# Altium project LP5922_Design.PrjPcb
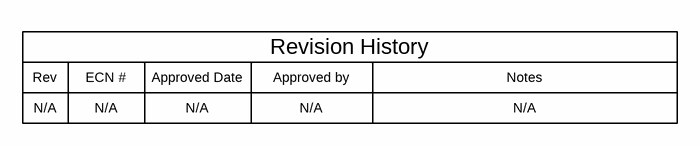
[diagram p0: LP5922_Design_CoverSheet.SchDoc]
CopyrightYear: 2016; PCB_Layout: Jari Niemelä; PCB_Rev: E1; PRJ_Customer: Public Release; PRJ_Engineer: Jari Niemelä; PRJ_Number: TIDA-01322; PRJ_Title: TIDA-01322; SCH_Rev: E1; TechSupport: http://www.ti.com/support; TID: N/A
3 sheets, 58 parts. Net scope: global (net labels, ports and power ports of the same name join across sheets).
Board file: LP5922_Design_PCB.PcbDoc
Sheets:
  LP5922_Design_CoverSheet.SchDoc
  LP5922_Design_BlankSheet.SchDoc
  LP5922_Design_EVM_Hardware.SchDoc

## Sheet LP5922_Design_CoverSheet.SchDoc
size 431 x 279 mm; Date: Not shown in title block; ApprovedBy: Not shown in title block; CheckedBy: Not shown in title block; Author: Not shown in title block; CompanyName: Not shown in title block; Engineer: Not shown in title block; Organization: Not shown in title block; Address1: Not shown in title block; Address2: Not shown in title block; Address3: Not shown in title block; Address4: Not shown in title block; DocumentNumber: 1; Revision: Use project parameter SCH_Rev; SheetNumber: 1; SheetTotal: 3; PageSetup: Record=PageOptions¦CenterHorizontal=True¦CenterVertical=True¦PrintScale=1.00¦XCorrection=1.00¦YCorrection=1.00¦PrintKind=0¦BorderSize=5000000¦LeftOffset=0¦BottomOffset=0¦Orientation=2¦PaperLength=1000¦PaperWidth=1000¦Scale=100¦PaperSource=15¦PrintQuality=600¦MediaType=1¦DitherType=10¦PaperKind=Letter¦PrintScaleMode=1

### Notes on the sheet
- Rev
- N/A
- ECN #
- Approved Date
- Approved by
- Revision History
- Notes

## Sheet LP5922_Design_BlankSheet.SchDoc
size 431 x 279 mm; Date: Not shown in title block; ApprovedBy: Not shown in title block; CheckedBy: Not shown in title block; Author: Not shown in title block; CompanyName: Not shown in title block; Engineer: Not shown in title block; Organization: Not shown in title block; Address1: Not shown in title block; Address2: Not shown in title block; Address3: Not shown in title block; Address4: Not shown in title block; DocumentNumber: 1; Revision: Use project parameter SCH_Rev; SheetNumber: 2; SheetTotal: 3; PageSetup: Record=PageOptions¦CenterHorizontal=True¦CenterVertical=True¦PrintScale=1.00¦XCorrection=1.00¦YCorrection=1.00¦PrintKind=0¦BorderSize=5000000¦LeftOffset=0¦BottomOffset=0¦Orientation=2¦PaperLength=1000¦PaperWidth=1000¦Scale=100¦PaperSource=15¦PrintQuality=600¦MediaType=1¦DitherType=10¦PrintScaleMode=1¦PaperKind=Letter
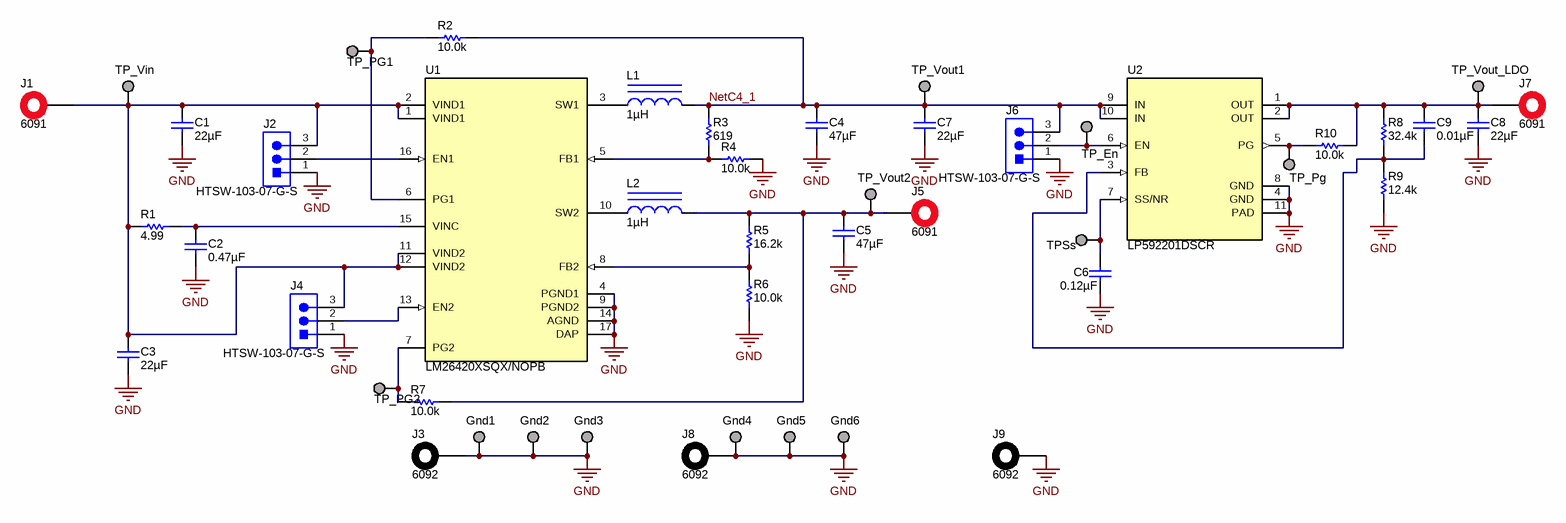
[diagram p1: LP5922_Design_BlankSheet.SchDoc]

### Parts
C1  ValueDisplayed: 22µF  [1206]  (hidden comment: C3216X5R0J226M)
C2  ValueDisplayed: 0.47µF  [0805_HV]  (hidden comment: 0805YC474JAT2A)
C3  ValueDisplayed: 22µF  [1206]  (hidden comment: C3216X5R0J226M)
C4  ValueDisplayed: 47µF  [1206]  (hidden comment: C3216X5R0J476M)
C5  ValueDisplayed: 47µF  [1206]  (hidden comment: C3216X5R0J476M)
C6  ValueDisplayed: 0.12µF  [0603]  (hidden comment: GRM188R71A124KA01D)
C7  ValueDisplayed: 22µF  [1210]  (hidden comment: C1210C226K9RACTU)
C8  ValueDisplayed: 22µF  [1210]  (hidden comment: C1210C226K9RACTU)
C9  ValueDisplayed: 0.01µF  [0603]  (hidden comment: GRM188R71H103KA01D)
Gnd1  Suggest using a net name here  [Keystone1502-2]  (value not drawn)
Gnd2  Suggest using a net name here  [Keystone1502-2]  (value not drawn)
Gnd3  Suggest using a net name here  [Keystone1502-2]  (value not drawn)
Gnd4  Suggest using a net name here  [Keystone1502-2]  (value not drawn)
Gnd5  Suggest using a net name here  [Keystone1502-2]  (value not drawn)
Gnd6  Suggest using a net name here  [Keystone1502-2]  (value not drawn)
J1  6091  [6091]
J2  HTSW-103-07-G-S  [Samtec_HTSW-103-07-G-S]
J3  6092  [6092]
J4  HTSW-103-07-G-S  [Samtec_HTSW-103-07-G-S]
J5  6091  [6091]
J6  HTSW-103-07-G-S  [Samtec_HTSW-103-07-G-S]
J7  6091  [6091]
J8  6092  [6092]
J9  6092  [6092]
L1  ValueDisplayed: 1µH  [DFE252012P]  (hidden comment: DFE252012PD-1R0M)
L2  ValueDisplayed: 1µH  [DFE252012P]  (hidden comment: DFE252012PD-1R0M)
R1  ValueDisplayed: 4.99  [0805_HV]  (hidden comment: CRCW08054R99FKEA)
R2  ValueDisplayed: 10.0k  [0402]  (hidden comment: CRCW040210K0DHEDP)
R3  ValueDisplayed: 619  [0402]  (hidden comment: CRCW0402619RFKED)
R4  ValueDisplayed: 10.0k  [0402]  (hidden comment: CRCW040210K0DHEDP)
R5  ValueDisplayed: 16.2k  [0402]  (hidden comment: CRCW040216K2FKED)
R6  ValueDisplayed: 10.0k  [0402]  (hidden comment: CRCW040210K0DHEDP)
R7  ValueDisplayed: 10.0k  [0402]  (hidden comment: CRCW040210K0DHEDP)
R8  ValueDisplayed: 32.4k  [0402]  (hidden comment: CRCW040232K4FKED)
R9  ValueDisplayed: 12.4k  [0402]  (hidden comment: CRCW040212K4FKED)
R10  ValueDisplayed: 10.0k  [0402]  (hidden comment: CRCW040210K0DHEDP)
TP_En  Suggest using a net name here  [Keystone1502-2]  (value not drawn)
TP_Pg  Suggest using a net name here  [Keystone1502-2]  (value not drawn)
TP_PG1  Suggest using a net name here  [Keystone1502-2]  (value not drawn)
TP_PG2  Suggest using a net name here  [Keystone1502-2]  (value not drawn)
TP_Vin  Suggest using a net name here  [Keystone1502-2]  (value not drawn)
TP_Vout1  Suggest using a net name here  [Keystone1502-2]  (value not drawn)
TP_Vout2  Suggest using a net name here  [Keystone1502-2]  (value not drawn)
TP_Vout_LDO  Suggest using a net name here  [Keystone1502-2]  (value not drawn)
TPSs  Suggest using a net name here  [Keystone1502-2]  (value not drawn)
U1  LM26420XSQX/NOPB  [RUM0016A]
U2  LP592201DSCR  [DSC0010J]

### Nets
GND: C1.2 C2.2 C3.2 C4.2 C5.2 C6.2 C7.2 C8.2 Gnd1.1 Gnd2.1 Gnd3.1 Gnd4.1 Gnd5.1 Gnd6.1 J2.1 J3.1 J4.1 J6.1 J8.1 J9.1 R4.1 R6.1 R9.1 U1.4(PGND1) U1.9(PGND2) U1.14(AGND) U1.17(DAP) U2.4(GND) U2.8(GND) U2.11(PAD)
NetC4_1: C4.1 C7.1 J6.3 L1.2 R2.2 R3.2 TP_Vout1.1 U2.9(IN) U2.10(IN)
NetC1_1: C1.1 C3.1 J1.1 J2.3 J4.3 R1.1 TP_Vin.1 U1.1(VIND1) U1.2(VIND1) U1.11(VIND2) U1.12(VIND2)
NetC2_1: C2.1 R1.2 U1.15(VINC)
NetC5_1: C5.1 J5.1 L2.2 R5.2 R7.2 TP_Vout2.1
NetC6_1: C6.1 TPSs.1 U2.7(SS/NR)
NetC8_1: C8.1 C9.1 J7.1 R8.2 R10.2 TP_Vout_LDO.1 U2.1(OUT) U2.2(OUT)
NetC9_2: C9.2 R8.1 R9.2 U2.3(FB)
NetJ2_2: J2.2 U1.16(EN1)
NetJ4_2: J4.2 U1.13(EN2)
NetJ6_2: J6.2 TP_En.1 U2.6(EN)
NetL1_1: L1.1 U1.3(SW1)
NetL2_1: L2.1 U1.10(SW2)
NetR2_1: R2.1 TP_PG1.1 U1.6(PG1)
NetR3_1: R3.1 R4.2 U1.5(FB1)
NetR5_1: R5.1 R6.2 U1.8(FB2)
NetR7_1: R7.1 TP_PG2.1 U1.7(PG2)
NetR10_1: R10.1 TP_Pg.1 U2.5(PG)

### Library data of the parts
C1 C3 = C3216X5R0J226M: CAP, CERM, 22 µF, 6.3 V, +/- 20%, X5R, 1206; Manufacturer: TDK; Polarized: N; CompType: Capacitor; Value: 22uF; U/M: EA; Cap_F: 0.000022; Tolerance_%: 20; ESR_ohm: 0.002; Value1: 0.002 ohm; VDC_V: 6.3; Value2: 6.3V; IRMS_A: 3.62; TaMin_C: -55; TaMax_C: 85; AEC Category: Q200
C2 = 0805YC474JAT2A: CAP, CERM, 0.47 µF, 16 V, +/- 5%, X7R, 0805; Manufacturer: AVX; Polarized: N; CompType: Capacitor; Value: 0.47uF; U/M: EA; Cap_F: 0.00000047; Tolerance_%: 5; ESR_ohm: 0.011; Value1: 0.011 ohm; VDC_V: 16; Value2: 16V; TaMin_C: -55; TaMax_C: 125; Cap_Case: 0805; AEC Category: Q200
C4 C5 = C3216X5R0J476M: CAP, CERM, 47 µF, 6.3 V, +/- 20%, X5R, 1206; Manufacturer: TDK; Polarized: N; CompType: Capacitor; Value: 47uF; U/M: EA; Cap_F: 0.000047; Tolerance_%: 20; ESR_ohm: 0.002; Value1: 0.002 ohm; VDC_V: 6.3; Value2: 6.3V; IRMS_A: 4.1; TaMin_C: -55; TaMax_C: 85; AEC Category: Q200
C6 = GRM188R71A124KA01D: CAP, CERM, 0.12 µF, 10 V, +/- 10%, X7R, 0603; Manufacturer: MuRata; Polarized: N; CompType: Capacitor; Value: 0.12uF; U/M: EA; Cap_F: 0.00000012; Tolerance_%: 10; Value1: Unknown; Value2: 10V; TaMin_C: -55; TaMax_C: 125; AEC Category: Q200
C7 C8 = C1210C226K9RACTU: CAP, CERM, 22 µF, 6.3 V, +/- 10%, X7R, 1210; Manufacturer: Kemet; Polarized: N; CompType: Capacitor; Value: 22uF; U/M: EA; Cap_F: 0.000022; Tolerance_%: 10; Value1: Unknown; VDC_V: 6.3; Value2: 6.3V; TaMin_C: -55; TaMax_C: 125; AEC Category: Q200
C9 = GRM188R71H103KA01D: CAP, CERM, 0.01 µF, 50 V, +/- 10%, X7R, 0603; Manufacturer: MuRata; Polarized: N; CompType: Capacitor; Value: 0.01uF; U/M: EA; Cap_F: 0.00000001; Tolerance_%: 10; Value1: Unknown; VDC_V: 50; Value2: 50V; TaMin_C: -55; TaMax_C: 125; AEC Category: Q200
Gnd1-Gnd6 TP_En TP_Pg TP_PG1 TP_PG2 TP_Vin TP_Vout1 TP_Vout2 TP_Vout_LDO TPSs = 1502-2: Terminal, Turret, TH, Double; Manufacturer: Keystone; CompType: Turret Terminal; U/M: EA
J1 J5 J7 = 6091: Standard Banana Jack, Insulated, Red; Manufacturer: Keystone; SymbolCreator: a0412235; CompType: Connector
J2 J4 J6 = HTSW-103-07-G-S: Header, 100mil, 3x1, Gold, TH; Manufacturer: Samtec; SymbolCreator: a0799628
J3 J8 J9 = 6092: Standard Banana Jack, Insulated, Black; Manufacturer: Keystone; SymbolCreator: a0412235; CompType: Connector
L1 L2 = DFE252012PD-1R0M: Inductor, Shielded, 1 µH, 3.8 A, 0.035 ohm, AEC-Q200 Grade 1, SMD; Manufacturer: MuRata Toko; Value: 1uH; Ind_H: 1.0E-6; Imax_A: 3.8; Irms: 3.8A @ 40C rise; Isat: 4.5A @ 30% inductance drop; DCR_ohm: 0.035; Value2: 3.8A; AEC Category: Q200; AEC Qualified: Y; AEC Grade: 1
R1 = CRCW08054R99FKEA: RES, 4.99, 1%, 0.125 W, 0805; Manufacturer: Vishay-Dale; CompType: Resistor; Value: 4.99; Value_Code: 4R99; Tolerance_%: 1; Power_W: 0.125; Value2: 0.125W; VDC_V: 150; TempCo: 100 ppm/C; EIA_Code: E96; U/M: EA; AEC Category: Q200
R2 R4 R6 R7 R10 = CRCW040210K0DHEDP: RES, 10.0 k, 0.5%, 0.063 W, 0402; Manufacturer: Vishay-Dale; CompType: Resistor; Value: 10.0k; Res_ohm: 10000; Value_Code: 10k0; Tolerance_%: 0.5; Power_W: 0.063; Value2: 0.063W; VDC_V: 50; TempCo: 50 ppm/C; EIA_Code: E192; U/M: EA; AEC Category: Q200
R3 = CRCW0402619RFKED: RES, 619, 1%, 0.063 W, 0402; Manufacturer: Vishay-Dale; CompType: Resistor; Value: 619; Value_Code: 619R; Tolerance_%: 1; Power_W: 0.063; Value2: 0.063W; VDC_V: 50; TempCo: 100 ppm/C; EIA_Code: E96; U/M: EA; AEC Category: Q200
R5 = CRCW040216K2FKED: RES, 16.2 k, 1%, 0.063 W, 0402; Manufacturer: Vishay-Dale; CompType: Resistor; Value: 16.2k; Res_ohm: 16200; Value_Code: 16k2; Tolerance_%: 1; Power_W: 0.063; Value2: 0.063W; VDC_V: 50; TempCo: 100 ppm/C; EIA_Code: E96; U/M: EA; AEC Category: Q200
R8 = CRCW040232K4FKED: RES, 32.4 k, 1%, 0.063 W, 0402; Manufacturer: Vishay-Dale; CompType: Resistor; Value: 32.4k; Res_ohm: 32400; Value_Code: 32k4; Tolerance_%: 1; Power_W: 0.063; Value2: 0.063W; VDC_V: 50; TempCo: 100 ppm/C; EIA_Code: E96; U/M: EA; AEC Category: Q200
R9 = CRCW040212K4FKED: RES, 12.4 k, 1%, 0.063 W, 0402; Manufacturer: Vishay-Dale; CompType: Resistor; Value: 12.4k; Res_ohm: 12400; Value_Code: 12k4; Tolerance_%: 1; Power_W: 0.063; Value2: 0.063W; VDC_V: 50; TempCo: 100 ppm/C; EIA_Code: E96; U/M: EA; AEC Category: Q200
U1 = LM26420XSQX/NOPB: Dual 2-A, High Frequency Synchronous Buck Regulator, RUM0016A (WQFN-16); Alternate PartNumber: LM26420XSQ/NOPB; Manufacturer: Texas Instruments; SymbolCreator: Altium; SizeArea_mm2: 16; SizeAreaWB_mm2: 25; SizeX_mm: 4; SizeZ_mm: 0.8; CompType: IC; U/M: EA
U2 = LP592201DSCR: LP592201, DSC0010J; Alternate PartNumber: LP592201DSCT; Manufacturer: Texas Instruments; SymbolCreator: Altium; SizeX_mm: 3; SizeZ_mm: 0.8; CompType: IC; U/M: EA

## Sheet LP5922_Design_EVM_Hardware.SchDoc
size 431 x 279 mm; Date: Not shown in title block; ApprovedBy: Not shown in title block; CheckedBy: Not shown in title block; Author: Not shown in title block; CompanyName: Not shown in title block; Engineer: Not shown in title block; Organization: Not shown in title block; Address1: Not shown in title block; Address2: Not shown in title block; Address3: Not shown in title block; Address4: Not shown in title block; DocumentNumber: 1; Revision: Use project parameter SCH_Rev; SheetNumber: 3; SheetTotal: 3; PageSetup: Record=PageOptions¦CenterHorizontal=True¦CenterVertical=True¦PrintScale=1.00¦XCorrection=1.00¦YCorrection=1.00¦PrintKind=0¦BorderSize=5000000¦LeftOffset=0¦BottomOffset=0¦Orientation=2¦PaperLength=1000¦PaperWidth=1000¦Scale=100¦PaperSource=15¦PrintQuality=600¦MediaType=1¦DitherType=10¦PaperKind=Letter¦PrintScaleMode=1
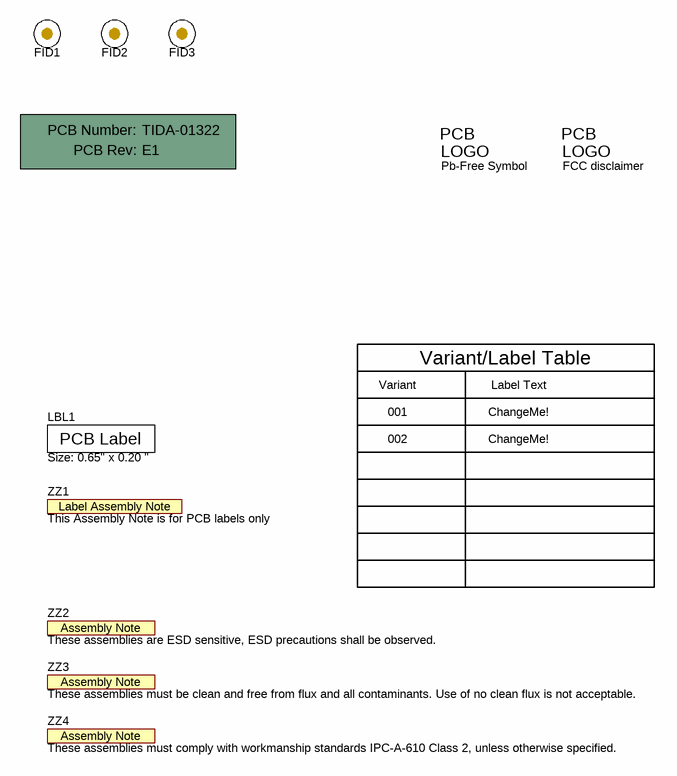
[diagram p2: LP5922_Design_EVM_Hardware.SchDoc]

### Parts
!PCB  Printed Circuit Board  (value not drawn)  (mechanical)
FID1  Fiducial  [Fiducial10-20]  (value not drawn)
FID2  Fiducial  [Fiducial10-20]  (value not drawn)
FID3  Fiducial  [Fiducial10-20]  (value not drawn)
LBL1  Size: 0.65" x 0.20 "  [Label_650x200]
Logo2  Pb-Free Symbol  [Pb-Free_Overlay_Small]  (no BOM)
Logo3  FCC disclaimer  [FCC_disclaimer]  (no BOM)
ZZ1  This Assembly Note is for PCB labels only  [AssemblyNoteLabel]  (no BOM)
ZZ2  These assemblies are ESD sensitive, ESD precautions shall be observed.  [AssemblyNote]  (no BOM)
ZZ3  These assemblies must be clean and free from flux and all contaminants. Use of no clean flux is not acceptable.  [AssemblyNote]  (no BOM)
ZZ4  These assemblies must comply with workmanship standards IPC-A-610 Class 2, unless otherwise specified.  [AssemblyNote]  (no BOM)

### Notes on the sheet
- Variant
- Variant/Label Table
- Label Text
- 001
- 002
- ChangeMe!

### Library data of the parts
!PCB = PCB: Manufacturer: Any; PartNumber: TIDA-01322; SymbolCreator: a0412235
FID1-FID3 = Fiducial: Fiducial mark.  There is nothing to buy or mount.; SymbolCreator: codlsc
LBL1 = THT-14-423-10: Thermal Transfer Printable Labels, 0.650" W x 0.200" H - 10,000 per roll; Manufacturer: Brady; SymbolCreator: a0412235; CompType: Label
Logo2 = Pb-Free: SymbolCreator: a0412235
Logo3 = FCC_disclaimer: SymbolCreator: codlsc
ZZ1 = AssemblyNoteLabel: SymbolCreator: a0412235
ZZ2-ZZ4 = AssemblyNote: SymbolCreator: codlsc

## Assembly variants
001: not fitted FID1 FID2 FID3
